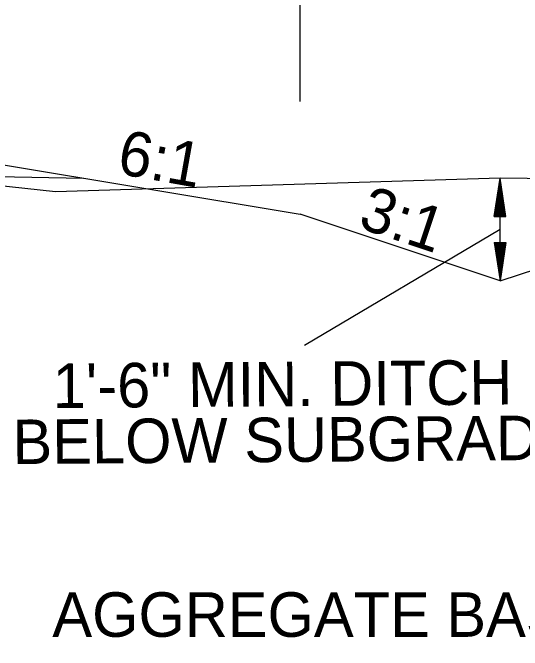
# Model space of a CAD drawing. Extents: x 6848689 to 6848907, y 1900908 to 1901005.
# Drawn here: x 6848766.91 to 6848774.34, y 1900920.07 to 1900929.37 of the extents above; entities that cross this region are included whole.
import ezdxf

# ---------------------------------------------------------------- set-up
doc = ezdxf.new("R2010")
doc.units = 0
for name, color, linetype in [('Default', 7, 'Continuous'), ('R_Draft', 7, 'Continuous'), ('R_No Plot', 7, 'Continuous')]:
    doc.layers.add(name, color=color, linetype=linetype)

msp = doc.modelspace()

# ---------------------------------------------------------------- linework, layer by layer
at = {"layer": 'Default'}
for p, q in [((6848761.0918, 1900928.102), (6848771.104, 1900926.4335)), ((6848756.124, 1900927.1977), (6848767.9358, 1900926.9615)), ((6848774.019, 1900925.4618), (6848778.3541, 1900926.9068)), ((6848774.019, 1900925.4618), (6848771.104, 1900926.4335))]:
    msp.add_line(p, q, dxfattribs=at)
msp.add_lwpolyline([(6848778.3541, 1900926.9068), (6848774.019, 1900926.9618), (6848767.5364, 1900926.7619), (6848765.9191, 1900926.935)], dxfattribs=at)
at = {"layer": 'R_Draft'}
for p, q in [((6848773.9353, 1900926.4033), (6848774.019, 1900926.9618)), ((6848774.1028, 1900926.4033), (6848774.019, 1900926.9618)), ((6848773.9492, 1900926.4033), (6848774.019, 1900926.8685)), ((6848774.0889, 1900926.4033), (6848774.019, 1900926.8685)), ((6848773.9635, 1900926.4033), (6848774.019, 1900926.7724)), ((6848774.0746, 1900926.4033), (6848774.019, 1900926.7724)), ((6848773.9774, 1900926.4033), (6848774.019, 1900926.6795)), ((6848774.0607, 1900926.4033), (6848774.019, 1900926.6795)), ((6848773.992, 1900926.4033), (6848774.019, 1900926.5848)), ((6848774.0464, 1900926.4033), (6848774.019, 1900926.5848)), ((6848774.0059, 1900926.4033), (6848774.019, 1900926.4915)), ((6848774.0322, 1900926.4033), (6848774.019, 1900926.4915)), ((6848773.9353, 1900926.4033), (6848774.1028, 1900926.4033)), ((6848773.9353, 1900926.0203), (6848774.019, 1900925.4618)), ((6848773.9353, 1900926.0203), (6848774.1028, 1900926.0203)), ((6848773.9492, 1900926.0203), (6848774.019, 1900925.5551)), ((6848773.9635, 1900926.0203), (6848774.019, 1900925.6511)), ((6848773.9774, 1900926.0203), (6848774.019, 1900925.7441)), ((6848773.992, 1900926.0203), (6848774.019, 1900925.8388)), ((6848774.0059, 1900926.0203), (6848774.019, 1900925.9321)), ((6848774.1028, 1900926.0203), (6848774.019, 1900925.4618)), ((6848774.0464, 1900926.0203), (6848774.019, 1900925.8388)), ((6848774.0746, 1900926.0203), (6848774.019, 1900925.6511)), ((6848774.0889, 1900926.0203), (6848774.019, 1900925.5551)), ((6848774.0607, 1900926.0203), (6848774.019, 1900925.7441)), ((6848774.0322, 1900926.0203), (6848774.019, 1900925.9321))]:
    msp.add_line(p, q, dxfattribs=at)
at = {"layer": 'R_No Plot'}
for p, q in [((6848771.104, 1900928.0811), (6848771.104, 1900936.5831)), ((6848774.019, 1900925.4618), (6848774.019, 1900926.9618)), ((6848774.019, 1900926.2118), (6848771.169, 1900924.518))]:
    msp.add_line(p, q, dxfattribs=at)

# ---------------------------------------------------------------- texts
at = {"layer": 'R_Draft'}
for s, rotation, p in [('6:1', 349.87726, (6848768.4148, 1900927.0316)), ('3:1', 341.60837, (6848771.928, 1900926.2455)), ('1\'-6" MIN. DITCH', 0.45446, (6848767.4969, 1900923.6067)), ('BELOW SUBGRADE', 0.45446, (6848766.9096, 1900922.7883))]:
    msp.add_text(s, height=0.65, rotation=rotation, dxfattribs=at).set_placement(p)
msp.add_text('AGGREGATE BASE CRSE. (CL. 7)', height=0.65, dxfattribs=at).set_placement((6848767.4886, 1900920.2693))

doc.saveas('drawing.dxf')
